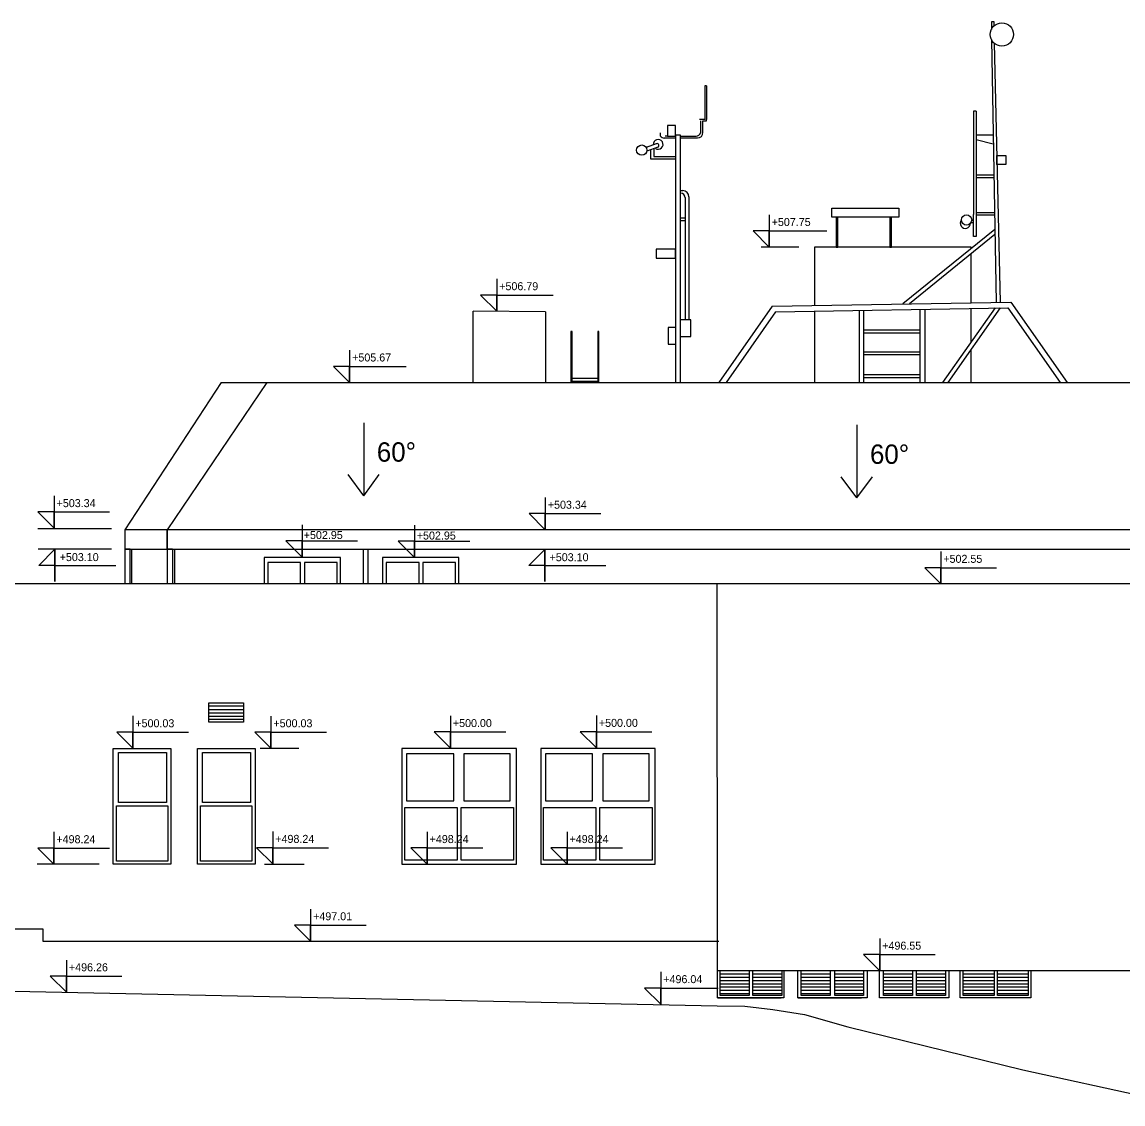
# Model space of a CAD drawing. Extents: x 96.5 to 160.8, y 493.2 to 511.4.
# Drawn here: x 124.93 to 141.98, y 494.5 to 511.26 of the extents above; entities that cross this region are included whole.
import ezdxf

# ---------------------------------------------------------------- set-up
doc = ezdxf.new("R2010")
doc.units = 0
for name, color, linetype in [('A-DETL-THIN', 7, 'Continuous'), ('antena', 7, 'Continuous'), ('ocelova_konstrukce', 7, 'Continuous'), ('okap', 7, 'Continuous'), ('okna', 7, 'Continuous'), ('strecha_sikma', 7, 'Continuous'), ('teren', 7, 'Continuous'), ('vyustky_vzduchotechniky', 7, 'Continuous'), ('zakl_tenka', 7, 'Continuous'), ('zebrik', 7, 'Continuous'), ('znaceni', 7, 'Continuous')]:
    doc.layers.add(name, color=color, linetype=linetype)

msp = doc.modelspace()

# ---------------------------------------------------------------- linework, layer by layer
at = {"layer": 'A-DETL-THIN'}
for p, q in [((137.541, 507.774), (137.566, 507.774)), ((138.371, 507.774), (138.396, 507.774))]:
    msp.add_line(p, q, dxfattribs=at)
at = {"layer": 'antena'}
for p, q in [((139.986, 511.264), (139.946, 511.264)), ((139.946, 511.264), (139.946, 511.15)), ((139.986, 511.204), (139.986, 511.264)), ((139.946, 510.992), (140.017, 506.921)), ((139.986, 510.938), (140.08, 506.923)), ((135.529, 510.273), (135.504, 510.273)), ((135.504, 510.273), (135.504, 509.753)), ((135.529, 510.273), (135.529, 509.753)), ((139.708, 509.882), (139.668, 509.882)), ((139.668, 509.882), (139.668, 508.281)), ((139.708, 509.882), (139.708, 507.941)), ((135.052, 509.659), (134.927, 509.659)), ((134.927, 509.659), (134.927, 509.495)), ((135.052, 509.495), (135.052, 509.659)), ((135.504, 509.753), (135.424, 509.753)), ((135.441, 509.548), (135.441, 509.732)), ((135.476, 509.552), (135.476, 509.732)), ((135.476, 509.732), (135.529, 509.732)), ((135.529, 509.732), (135.529, 509.753)), ((134.817, 509.495), (134.817, 509.545)), ((135.052, 509.467), (134.874, 509.467)), ((134.927, 509.495), (134.891, 509.495)), ((134.927, 509.495), (135.052, 509.495)), ((135.13, 509.51), (135.052, 509.51)), ((135.052, 509.51), (135.052, 505.68)), ((135.13, 505.68), (135.13, 509.51)), ((135.13, 509.495), (135.37, 509.495)), ((135.392, 509.467), (135.13, 509.467)), ((139.971, 509.51), (139.708, 509.51)), ((134.754, 509.379), (134.596, 509.322)), ((134.775, 509.323), (134.606, 509.262)), ((134.714, 509.301), (134.714, 509.181)), ((139.974, 509.37), (139.708, 509.441)), ((134.671, 509.141), (134.671, 509.285)), ((135.052, 509.141), (134.671, 509.141)), ((134.714, 509.181), (135.052, 509.181)), ((140.027, 509.198), (140.167, 509.198)), ((140.027, 509.058), (140.027, 509.198)), ((140.167, 509.198), (140.167, 509.058)), ((140.167, 509.058), (140.027, 509.058)), ((139.982, 508.89), (139.708, 508.89)), ((139.983, 508.85), (139.708, 508.85)), ((135.163, 508.651), (135.13, 508.651)), ((135.2, 508.544), (135.2, 506.652)), ((135.26, 508.554), (135.26, 506.652)), ((139.668, 507.941), (139.668, 508.281)), ((139.992, 508.31), (139.708, 508.31)), ((135.2, 508.224), (135.13, 508.224)), ((135.2, 508.184), (135.13, 508.184)), ((139.668, 508.155), (139.628, 508.155)), ((139.668, 508.19), (139.64, 508.19)), ((139.993, 508.27), (139.708, 508.27)), ((139.997, 508.05), (138.572, 506.896)), ((139.998, 507.97), (138.675, 506.898)), ((139.708, 507.941), (139.668, 507.941)), ((136.961, 507.774), (136.38, 507.774)), ((135.052, 507.743), (134.751, 507.743)), ((134.751, 507.743), (134.751, 507.603)), ((134.751, 507.603), (135.052, 507.603)), ((135.052, 507.603), (135.052, 507.743)), ((140.002, 506.834), (139.189, 505.68)), ((140.082, 506.836), (139.268, 505.68)), ((135.29, 506.652), (135.13, 506.652)), ((135.29, 506.392), (135.29, 506.652)), ((135.052, 506.532), (134.937, 506.532)), ((134.937, 506.532), (134.937, 506.272)), ((134.937, 506.272), (135.052, 506.272)), ((135.13, 506.392), (135.29, 506.392))]:
    msp.add_line(p, q, dxfattribs=at)
for centre, radius in [((140.107, 511.071), 0.18), ((134.528, 509.279), 0.08), ((139.56, 508.197), 0.08)]:
    msp.add_circle(centre, radius, dxfattribs=at)
for centre, radius, start, end in [((134.874, 509.538), 0.0711, 217.4733, 270), ((135.37, 509.569), 0.0741, 270, 343.4001), ((135.392, 509.552), 0.0849, 270, 0), ((134.782, 509.368), 0.0766, 236.4718, 185.0362), ((134.765, 509.351), 0.03, 290, 110), ((135.163, 508.554), 0.0972, 0, 90), ((135.13, 508.541), 0.0704, 0, 90), ((139.542, 508.147), 0.0797, 140.5807, 359.4193)]:
    msp.add_arc(centre, radius, start, end, dxfattribs=at)
at = {"layer": 'ocelova_konstrukce'}
for p, q in [((137.472, 508.382), (138.512, 508.382)), ((137.472, 508.242), (137.472, 508.382)), ((138.512, 508.382), (138.512, 508.242)), ((138.512, 508.242), (137.472, 508.242)), ((137.566, 508.242), (137.541, 508.242)), ((137.541, 508.242), (137.541, 507.774)), ((137.566, 507.774), (137.566, 508.242)), ((138.396, 508.242), (138.371, 508.242)), ((138.371, 508.242), (138.371, 507.774)), ((138.396, 507.774), (138.396, 508.242)), ((136.548, 506.861), (140.247, 506.925)), ((140.247, 506.925), (141.119, 505.68)), ((136.548, 506.861), (135.721, 505.68)), ((136.601, 506.775), (135.834, 505.68)), ((136.601, 506.775), (140.2, 506.838)), ((137.897, 506.798), (137.897, 505.68)), ((137.967, 505.68), (137.967, 506.799)), ((138.844, 505.68), (138.844, 506.814)), ((138.914, 506.815), (138.914, 505.68)), ((140.2, 506.838), (141.01, 505.68)), ((137.967, 506.494), (138.844, 506.493)), ((138.844, 506.443), (137.967, 506.446)), ((137.967, 506.157), (138.844, 506.157)), ((138.844, 506.107), (137.967, 506.107)), ((137.967, 505.804), (138.844, 505.804)), ((138.844, 505.754), (137.967, 505.754))]:
    msp.add_line(p, q, dxfattribs=at)
at = {"layer": 'okap'}
for p, q in [((126.521, 503.395), (126.52, 503.098)), ((127.257, 503.098), (127.257, 502.56))]:
    msp.add_line(p, q, dxfattribs=at)
for points in [[(126.52, 503.098), (127.176, 503.098), (127.177, 503.396), (126.521, 503.395)], [(126.601, 502.56), (126.601, 503.098), (126.52, 503.098), (126.52, 502.56)], [(127.257, 503.098), (127.176, 503.098), (127.176, 502.56)], [(130.21, 503.098), (130.21, 502.56)], [(130.29, 502.56), (130.29, 503.098)]]:
    msp.add_lwpolyline(points, dxfattribs=at)
for points in [[(148.677, 503.395), (127.176, 503.395), (127.176, 503.098), (148.677, 503.098)], [(127.176, 503.395), (127.176, 503.395), (127.176, 503.098), (127.176, 503.098)]]:
    msp.add_lwpolyline(points, close=True, dxfattribs=at)
at = {"layer": 'okna'}
for points in [[(129.243, 502.56), (129.243, 502.892), (128.735, 502.892), (128.735, 502.56)], [(129.809, 502.56), (129.809, 502.892), (129.301, 502.892), (129.301, 502.56)], [(131.078, 502.56), (131.078, 502.892), (130.57, 502.892), (130.57, 502.56)], [(131.644, 502.56), (131.644, 502.892), (131.136, 502.892), (131.136, 502.56)]]:
    msp.add_lwpolyline(points, dxfattribs=at)
for points in [[(126.423, 499.949), (127.164, 499.949), (127.164, 499.172), (126.423, 499.172)], [(127.725, 499.949), (128.465, 499.949), (128.465, 499.172), (127.725, 499.172)], [(131.617, 499.927), (130.885, 499.927), (130.885, 499.201), (131.617, 499.201)], [(132.492, 499.927), (131.774, 499.927), (131.774, 499.201), (132.492, 499.201)], [(133.767, 499.927), (133.035, 499.927), (133.035, 499.201), (133.767, 499.201)], [(134.642, 499.927), (133.924, 499.927), (133.924, 499.201), (134.642, 499.201)], [(126.39, 499.121), (127.188, 499.121), (127.188, 498.265), (126.39, 498.265)], [(127.692, 499.121), (128.49, 499.121), (128.49, 498.265), (127.692, 498.265)], [(130.857, 499.098), (131.669, 499.098), (131.669, 498.28), (130.857, 498.28)], [(131.73, 499.098), (132.542, 499.098), (132.542, 498.28), (131.73, 498.28)], [(133.007, 499.098), (133.819, 499.098), (133.819, 498.28), (133.007, 498.28)], [(133.88, 499.098), (134.692, 499.098), (134.692, 498.28), (133.88, 498.28)]]:
    msp.add_lwpolyline(points, close=True, dxfattribs=at)
at = {"layer": 'strecha_sikma'}
for p, q in [((128.011, 505.68), (126.521, 503.395)), ((128.719, 505.68), (127.176, 503.395)), ((128.011, 505.68), (147.075, 505.68)), ((133.847, 505.695), (133.448, 505.695)), ((148.677, 503.395), (127.176, 503.395))]:
    msp.add_line(p, q, dxfattribs=at)
at = {"layer": 'teren'}
for p, q in [((124.521, 496.255), (135.697, 496.026)), ((135.697, 496.026), (136.125, 496.018)), ((136.125, 496.018), (136.558, 495.966)), ((136.558, 495.966), (137.048, 495.887)), ((137.048, 495.887), (137.723, 495.696)), ((137.723, 495.696), (140.434, 495.034)), ((140.434, 495.034), (142.837, 494.503))]:
    msp.add_line(p, q, dxfattribs=at)
at = {"layer": 'vyustky_vzduchotechniky'}
for p, q in [((127.819, 500.673), (128.359, 500.673)), ((127.819, 500.615), (128.359, 500.615)), ((127.819, 500.565), (128.359, 500.565)), ((127.819, 500.513), (128.359, 500.513)), ((127.819, 500.463), (128.359, 500.463)), ((135.742, 496.52), (136.19, 496.52)), ((136.251, 496.52), (136.699, 496.52)), ((136.998, 496.52), (137.446, 496.52)), ((137.517, 496.52), (137.965, 496.52)), ((138.274, 496.52), (138.722, 496.52)), ((138.785, 496.52), (139.233, 496.52)), ((139.509, 496.52), (139.989, 496.52)), ((140.037, 496.52), (140.517, 496.52)), ((135.742, 496.467), (136.19, 496.467)), ((135.742, 496.416), (136.19, 496.416)), ((135.742, 496.366), (136.19, 496.366)), ((136.251, 496.467), (136.699, 496.467)), ((136.251, 496.416), (136.699, 496.416)), ((136.251, 496.366), (136.699, 496.366)), ((136.998, 496.467), (137.446, 496.467)), ((136.998, 496.416), (137.446, 496.416)), ((136.998, 496.366), (137.446, 496.366)), ((137.517, 496.467), (137.965, 496.467)), ((137.517, 496.416), (137.965, 496.416)), ((137.517, 496.366), (137.965, 496.366)), ((138.274, 496.467), (138.722, 496.467)), ((138.274, 496.416), (138.722, 496.416)), ((138.274, 496.366), (138.722, 496.366)), ((138.785, 496.467), (139.233, 496.467)), ((138.785, 496.416), (139.233, 496.416)), ((138.785, 496.366), (139.233, 496.366)), ((139.509, 496.467), (139.989, 496.467)), ((139.509, 496.416), (139.989, 496.416)), ((139.509, 496.366), (139.989, 496.366)), ((140.037, 496.467), (140.517, 496.467)), ((140.037, 496.416), (140.517, 496.416)), ((140.037, 496.366), (140.517, 496.366)), ((135.742, 496.319), (136.19, 496.319)), ((135.742, 496.264), (136.19, 496.264)), ((135.742, 496.214), (136.19, 496.214)), ((136.251, 496.319), (136.699, 496.319)), ((136.251, 496.264), (136.699, 496.264)), ((136.251, 496.214), (136.699, 496.214)), ((136.998, 496.319), (137.446, 496.319)), ((136.998, 496.264), (137.446, 496.264)), ((136.998, 496.214), (137.446, 496.214)), ((137.517, 496.319), (137.965, 496.319)), ((137.517, 496.264), (137.965, 496.264)), ((137.517, 496.214), (137.965, 496.214)), ((138.274, 496.319), (138.722, 496.319)), ((138.274, 496.264), (138.722, 496.264)), ((138.274, 496.214), (138.722, 496.214)), ((138.785, 496.319), (139.233, 496.319)), ((138.785, 496.264), (139.233, 496.264)), ((138.785, 496.214), (139.233, 496.214)), ((139.509, 496.319), (139.989, 496.319)), ((139.509, 496.264), (139.989, 496.264)), ((139.509, 496.214), (139.989, 496.214)), ((140.037, 496.319), (140.517, 496.319)), ((140.037, 496.264), (140.517, 496.264)), ((140.037, 496.214), (140.517, 496.214)), ((135.702, 496.146), (136.686, 496.146)), ((136.948, 496.146), (137.932, 496.146))]:
    msp.add_line(p, q, dxfattribs=at)
msp.add_lwpolyline([(127.819, 500.719), (128.359, 500.719), (128.359, 500.419), (127.819, 500.419)], close=True, dxfattribs=at)
for points in [[(136.731, 496.567), (136.731, 496.146), (135.702, 496.146), (135.702, 496.567)], [(136.19, 496.567), (136.19, 496.183), (135.742, 496.183), (135.742, 496.567)], [(136.699, 496.567), (136.699, 496.183), (136.251, 496.183), (136.251, 496.567)], [(138.019, 496.567), (138.019, 496.146), (136.948, 496.146), (136.948, 496.567)], [(137.446, 496.567), (137.446, 496.183), (136.998, 496.183), (136.998, 496.567)], [(137.965, 496.567), (137.965, 496.183), (137.517, 496.183), (137.517, 496.567)], [(139.286, 496.567), (139.286, 496.146), (138.214, 496.146), (138.214, 496.567)], [(138.722, 496.567), (138.722, 496.183), (138.274, 496.183), (138.274, 496.567)], [(139.233, 496.567), (139.233, 496.183), (138.785, 496.183), (138.785, 496.567)], [(140.554, 496.567), (140.554, 496.146), (139.462, 496.146), (139.462, 496.567)], [(139.989, 496.567), (139.989, 496.183), (139.509, 496.183), (139.509, 496.567)], [(140.517, 496.567), (140.517, 496.183), (140.037, 496.183), (140.037, 496.567)]]:
    msp.add_lwpolyline(points, dxfattribs=at)
at = {"layer": 'zakl_tenka'}
for p, q in [((139.631, 507.774), (137.204, 507.774)), ((137.204, 507.774), (137.204, 506.872)), ((139.631, 507.754), (139.631, 507.774)), ((139.631, 506.915), (139.631, 507.673)), ((131.919, 505.68), (131.919, 506.786)), ((133.038, 506.774), (131.919, 506.786)), ((133.038, 506.774), (133.038, 505.68)), ((137.204, 506.785), (137.204, 505.68)), ((139.631, 506.308), (139.631, 506.828)), ((139.631, 505.68), (139.631, 506.195)), ((126.626, 503.098), (126.626, 502.56)), ((127.289, 503.098), (127.289, 502.56)), ((135.698, 502.56), (122.845, 502.56)), ((142.384, 502.56), (135.698, 502.56)), ((135.702, 496.567), (135.698, 502.56)), ((125.256, 497.213), (122.845, 497.213)), ((125.256, 497.021), (125.256, 497.213)), ((135.723, 497.021), (125.256, 497.021)), ((142.384, 496.567), (135.702, 496.567))]:
    msp.add_line(p, q, dxfattribs=at)
for points in [[(129.862, 502.56), (129.862, 502.969), (128.678, 502.969), (128.678, 502.56)], [(131.695, 502.56), (131.695, 502.969), (130.511, 502.969), (130.511, 502.56)]]:
    msp.add_lwpolyline(points, dxfattribs=at)
for points in [[(127.231, 498.216), (126.339, 498.216), (126.339, 500.01), (127.231, 500.01)], [(128.54, 498.216), (127.648, 498.216), (127.648, 500.01), (128.54, 500.01)], [(132.586, 500.01), (130.814, 500.01), (130.814, 498.216), (132.586, 498.216)], [(134.736, 500.01), (132.967, 500.01), (132.967, 498.216), (134.736, 498.216)]]:
    msp.add_lwpolyline(points, close=True, dxfattribs=at)
at = {"layer": 'zebrik'}
msp.add_line((133.448, 505.749), (133.847, 505.749), dxfattribs=at)
for points in [[(133.448, 505.68), (133.448, 506.47), (133.43, 506.47), (133.43, 505.68)], [(133.865, 505.68), (133.865, 506.47), (133.847, 506.47), (133.847, 505.68)]]:
    msp.add_lwpolyline(points, dxfattribs=at)
at = {"layer": 'znaceni'}
for p, q in [((136.502, 508.278), (136.502, 507.778)), ((136.502, 508.028), (136.252, 508.028)), ((136.252, 508.028), (136.502, 507.778)), ((136.502, 507.778), (136.502, 508.028)), ((136.502, 508.028), (137.398, 508.028)), ((132.281, 507.283), (132.281, 506.783)), ((132.281, 507.033), (132.031, 507.033)), ((132.031, 507.033), (132.281, 506.783)), ((132.281, 506.783), (132.281, 507.033)), ((132.281, 507.033), (133.157, 507.033)), ((130.003, 506.18), (130.003, 505.68)), ((130.003, 505.93), (129.753, 505.93)), ((129.753, 505.93), (130.003, 505.68)), ((130.003, 505.68), (130.003, 505.93)), ((130.003, 505.93), (130.879, 505.93)), ((130.221, 505.056), (130.221, 503.926)), ((137.86, 505.022), (137.86, 503.892)), ((130.221, 503.926), (129.98, 504.253)), ((130.221, 503.926), (130.461, 504.253)), ((137.86, 503.892), (137.619, 504.219)), ((137.86, 503.892), (138.101, 504.219)), ((125.424, 503.924), (125.424, 503.424)), ((133.034, 503.898), (133.034, 503.398)), ((125.424, 503.674), (125.174, 503.674)), ((125.174, 503.674), (125.424, 503.424)), ((125.424, 503.424), (125.424, 503.674)), ((125.424, 503.674), (126.283, 503.674)), ((133.034, 503.648), (132.784, 503.648)), ((132.784, 503.648), (133.034, 503.398)), ((133.034, 503.398), (133.034, 503.648)), ((133.034, 503.648), (133.893, 503.648)), ((126.316, 503.412), (125.173, 503.412)), ((129.265, 503.475), (129.265, 502.975)), ((131.007, 503.47), (131.007, 502.97)), ((129.265, 503.225), (129.015, 503.225)), ((129.015, 503.225), (129.265, 502.975)), ((129.265, 502.975), (129.265, 503.225)), ((129.265, 503.225), (130.124, 503.225)), ((131.007, 503.22), (130.757, 503.22)), ((130.757, 503.22), (131.007, 502.97)), ((131.007, 502.97), (131.007, 503.22)), ((131.007, 503.22), (131.867, 503.22)), ((126.313, 503.098), (125.177, 503.098)), ((125.188, 502.847), (125.438, 503.097)), ((125.438, 503.097), (125.438, 502.597)), ((125.438, 502.597), (125.438, 503.097)), ((125.438, 503.097), (125.438, 502.847)), ((132.777, 502.845), (133.027, 503.095)), ((133.027, 503.095), (133.027, 502.595)), ((133.027, 502.595), (133.027, 503.095)), ((133.027, 503.095), (133.027, 502.845)), ((139.162, 503.06), (139.162, 502.56)), ((125.438, 502.847), (125.188, 502.847)), ((125.438, 502.847), (125.188, 502.847)), ((125.438, 502.597), (125.438, 502.847)), ((125.438, 502.847), (126.383, 502.847)), ((125.438, 502.847), (126.383, 502.847)), ((133.027, 502.845), (132.777, 502.845)), ((133.027, 502.845), (132.777, 502.845)), ((133.027, 502.595), (133.027, 502.845)), ((133.027, 502.845), (133.972, 502.845)), ((133.027, 502.845), (133.972, 502.845)), ((139.162, 502.81), (138.912, 502.81)), ((138.912, 502.81), (139.162, 502.56)), ((139.162, 502.56), (139.162, 502.81)), ((139.162, 502.81), (140.023, 502.81)), ((126.644, 500.514), (126.644, 500.014)), ((128.783, 500.513), (128.783, 500.013)), ((131.563, 500.516), (131.563, 500.016)), ((133.825, 500.519), (133.825, 500.019)), ((126.644, 500.264), (126.394, 500.264)), ((126.394, 500.264), (126.644, 500.014)), ((126.644, 500.014), (126.644, 500.264)), ((126.644, 500.264), (127.505, 500.264)), ((128.783, 500.263), (128.533, 500.263)), ((128.533, 500.263), (128.783, 500.013)), ((128.783, 500.013), (128.783, 500.263)), ((128.783, 500.263), (129.644, 500.263)), ((131.563, 500.266), (131.313, 500.266)), ((131.313, 500.266), (131.563, 500.016)), ((131.563, 500.016), (131.563, 500.266)), ((131.563, 500.266), (132.425, 500.266)), ((133.825, 500.269), (133.575, 500.269)), ((133.575, 500.269), (133.825, 500.019)), ((133.825, 500.019), (133.825, 500.269)), ((133.825, 500.269), (134.687, 500.269)), ((128.619, 500.013), (129.214, 500.013)), ((128.812, 498.723), (128.812, 498.223)), ((131.203, 498.72), (131.203, 498.22)), ((125.422, 498.717), (125.422, 498.217)), ((133.371, 498.719), (133.371, 498.219)), ((125.422, 498.467), (125.172, 498.467)), ((125.172, 498.467), (125.422, 498.217)), ((125.422, 498.217), (125.422, 498.467)), ((125.422, 498.467), (126.283, 498.467)), ((128.812, 498.473), (128.562, 498.473)), ((128.562, 498.473), (128.812, 498.223)), ((128.812, 498.223), (128.812, 498.473)), ((128.812, 498.473), (129.674, 498.473)), ((131.203, 498.47), (130.953, 498.47)), ((130.953, 498.47), (131.203, 498.22)), ((131.203, 498.22), (131.203, 498.47)), ((131.203, 498.47), (132.064, 498.47)), ((133.371, 498.469), (133.121, 498.469)), ((133.121, 498.469), (133.371, 498.219)), ((133.371, 498.219), (133.371, 498.469)), ((133.371, 498.469), (134.232, 498.469)), ((126.121, 498.216), (125.161, 498.216)), ((128.682, 498.216), (129.3, 498.216)), ((129.399, 497.523), (129.399, 497.023)), ((129.399, 497.273), (129.149, 497.273)), ((129.149, 497.273), (129.399, 497.023)), ((129.399, 497.023), (129.399, 497.273)), ((129.399, 497.273), (130.26, 497.273)), ((138.215, 497.068), (138.215, 496.568)), ((125.615, 496.733), (125.615, 496.233)), ((138.215, 496.818), (137.965, 496.818)), ((137.965, 496.818), (138.215, 496.568)), ((138.215, 496.568), (138.215, 496.818)), ((138.215, 496.818), (139.076, 496.818)), ((134.823, 496.549), (134.823, 496.049)), ((125.615, 496.483), (125.365, 496.483)), ((125.365, 496.483), (125.615, 496.233)), ((125.615, 496.233), (125.615, 496.483)), ((125.615, 496.483), (126.476, 496.483)), ((134.823, 496.299), (134.573, 496.299)), ((134.573, 496.299), (134.823, 496.049)), ((134.823, 496.049), (134.823, 496.299)), ((134.823, 496.299), (135.713, 496.299))]:
    msp.add_line(p, q, dxfattribs=at)

# ---------------------------------------------------------------- texts
for s, height, p in [('+507.75', 0.124, (136.541, 508.104)), ('+506.79', 0.124, (132.32, 507.109)), ('+505.67', 0.124, (130.042, 506.005)), ('60°', 0.3, (130.424, 504.453)), ('60°', 0.3, (138.064, 504.419)), ('+503.34', 0.124, (125.463, 503.749)), ('+503.34', 0.124, (133.073, 503.724)), ('+502.95', 0.124, (129.292, 503.255)), ('+502.95', 0.124, (131.043, 503.247)), ('+503.10', 0.124, (125.511, 502.913)), ('+503.10', 0.124, (133.1, 502.911)), ('+502.55', 0.124, (139.2, 502.886)), ('+500.03', 0.124, (126.683, 500.339)), ('+500.03', 0.124, (128.822, 500.339)), ('+500.00', 0.124, (131.602, 500.342)), ('+500.00', 0.124, (133.864, 500.345)), ('+498.24', 0.124, (125.46, 498.543)), ('+498.24', 0.124, (128.851, 498.548)), ('+498.24', 0.124, (131.242, 498.545)), ('+498.24', 0.124, (133.409, 498.545)), ('+497.01', 0.124, (129.437, 497.349)), ('+496.55', 0.124, (138.254, 496.894)), ('+496.26', 0.124, (125.654, 496.559)), ('+496.04', 0.124, (134.862, 496.375))]:
    msp.add_text(s, height=height, dxfattribs=at).set_placement(p)

doc.saveas('drawing.dxf')
